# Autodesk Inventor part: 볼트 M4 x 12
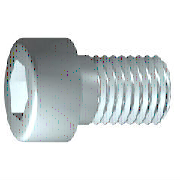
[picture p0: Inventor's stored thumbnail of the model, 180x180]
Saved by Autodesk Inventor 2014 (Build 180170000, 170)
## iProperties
IsCustomPart: 0
Created: 2012-02
Part Number: 볼트 M4 x 12
Material: 스테인리스강
Description: 6각 소켓 머리 캡 나사
Document SubType Name: Modeling
Standard: ISO 4762
Designer: mduedu
Standard Revision: Fourth edition 2004-03-01
Standards Organization: ISO
Language: ko-KR
Size Designation: M4 x 12
Categories: <MemberInstance><Categories><Category DisplayName="조임쇠" InternalName="e4da775c-781d-43d5-af7c-5136215cf5a6" Mnemonic="FSTN"><Category DisplayName="볼트" InternalN
Density: 8.08 g/cm^3
Appearance: 반광택
Author: mduedu
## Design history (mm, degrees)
sketch "스케치1"
  geometry: L1 (-1, 0)-(12, 0); L2 (12, 0)-(12, 2); L3 (12, 2)-(1.75, 2); L4 (1.75, 2)-(1.32, 2); L5 (1.32, 2)-(0, 2); L6 (0, 2)-(0, 3.5); L7 (0, 3.5)-(-4, 3.5); L8 (-4, 3.5)-(-4, 1.732); L9 (-4, 1.732)-(-2, 1.732); L10 (-2, 1.732)-(-1, 0); L11 (-7.2, 0)-(15.2, 0) reference; L12 (0, -0.7)-(0, 4.2) reference; L13 (1.75, 2)-(0, 2)
  constraints: 22 end point, 6 parallel, 2 collinear, 2 perpendicular, 1 horizontal, 1 point on line
  dimensions: "d1" = 10.25 distance from line of L3.end L2 (= GEL); "d2" = 0.42952 distance of L4.end L3.end (computed from GAL); "d3" = 4 distance between parallel lines of L8 L6 (= KOH); "d4" = 2 distance of L8.end L9.end (= INTI); "d5" = 60 deg angle of L10 L1; "d6" = 4 diameter of L3 L1 (= GD); "d7" = 4 diameter of L5 L1 (= BDM); "d8" = 3.4641 diameter of L9 L1 (= 1.1547 x SW); "d9" = 7 diameter of L7 L1 (= KOD); "d26" = 12 distance between parallel lines of L12 L2 (= NLG)
revolve "본체" sketch "스케치1" stored, may be unused: angle "d10" = 90 deg
sketch "스케치2"
  geometry: L1 (0, -4.9)-(0, 4.9) reference; L2 (-4.9, 0)-(4.9, 0) reference; L3 (1.732, 0)-(0.866, -1.5); L4 (0.866, -1.5)-(-0.866, -1.5); L5 (-0.866, -1.5)-(-1.732, 0); L6 (-1.732, 0)-(-0.866, 1.5); L7 (-0.866, 1.5)-(0.866, 1.5); L8 (0.866, 1.5)-(1.732, 0); 2 further points
  constraints: 12 end point, 1 coincident, 1 horizontal alignment, 1 point on line, 12 other
extrude "슬롯" join sketch "스케치2" stored distance "d11" = 10; taper "d12" = 0 deg
workplane "Work Plane1"
fillet "Fillet2" dims "d30" = 0.1 (= R)
body "Solid1"
fillet "모깎기1" dims "d17" = 0.4 (= RR)
feature "스레드" dims "d13" = 10.25 (= GEL), "d14" = 0
chamfer "모따기1" distance "d15" = 0.42941 (= -0.5 x SPD + 0.5 x GD); stored, may be unused: second distance "d16" = 0.42941 (= GUL), angle "d27" = 45 deg
other parameters: "GD" = 4 [user parameter; used in 2 equation terms], "NLG" = 12 [user parameter; used in 1 equation term], "GEL" = 10.25 [user parameter; used in 2 equation terms], "KOD" = 7 [user parameter; used in 1 equation term], "KOH" = 4 [user parameter; used in 1 equation term], "INTI" = 2 [user parameter; used in 1 equation term], "GAL" = 0.42941 (= 0.61345 x PTC) [user parameter; used in 1 equation term], "GUL" = 0.42941 (= 0.61345 x PTC) [user parameter; used in 1 equation term], "BDM" = 4 (= NND) [user parameter; used in 1 equation term], "SW" = 3 [user parameter; used in 2 equation terms], "RR" = 0.4 [user parameter; used in 1 equation term], "SPD" = 3.14117 (= NND - 1.2269 x PTC) [user parameter; used in 1 equation term], "d19" = 0, "d28" = 0, "d29" = 0, "R" = 0.1 [user parameter; used in 1 equation term], "TOA" = 30 deg [user parameter], "GD1" = 3.14117 (= THREADDIA - 1.2269 x PTC) [user parameter], "THREADDIA" = 4 [user parameter; used in 1 equation term], "FAWI" = 45 deg [user parameter], "TPU" = 14.28571 (computed from PTC) [user parameter], "PTC" = 0.7 [user parameter; used in 5 equation terms], "NND" = 4 [user parameter; used in 2 equation terms], "E0" = 3.465 (= 1.155 x SW) [user parameter]
